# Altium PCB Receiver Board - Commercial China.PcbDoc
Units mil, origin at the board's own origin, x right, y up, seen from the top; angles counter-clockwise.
Board outline 2000 x 1000 mil, 2 copper layers (Top Layer, Bottom Layer); 23 components, 21 nets, 121 pads, 26 vias.
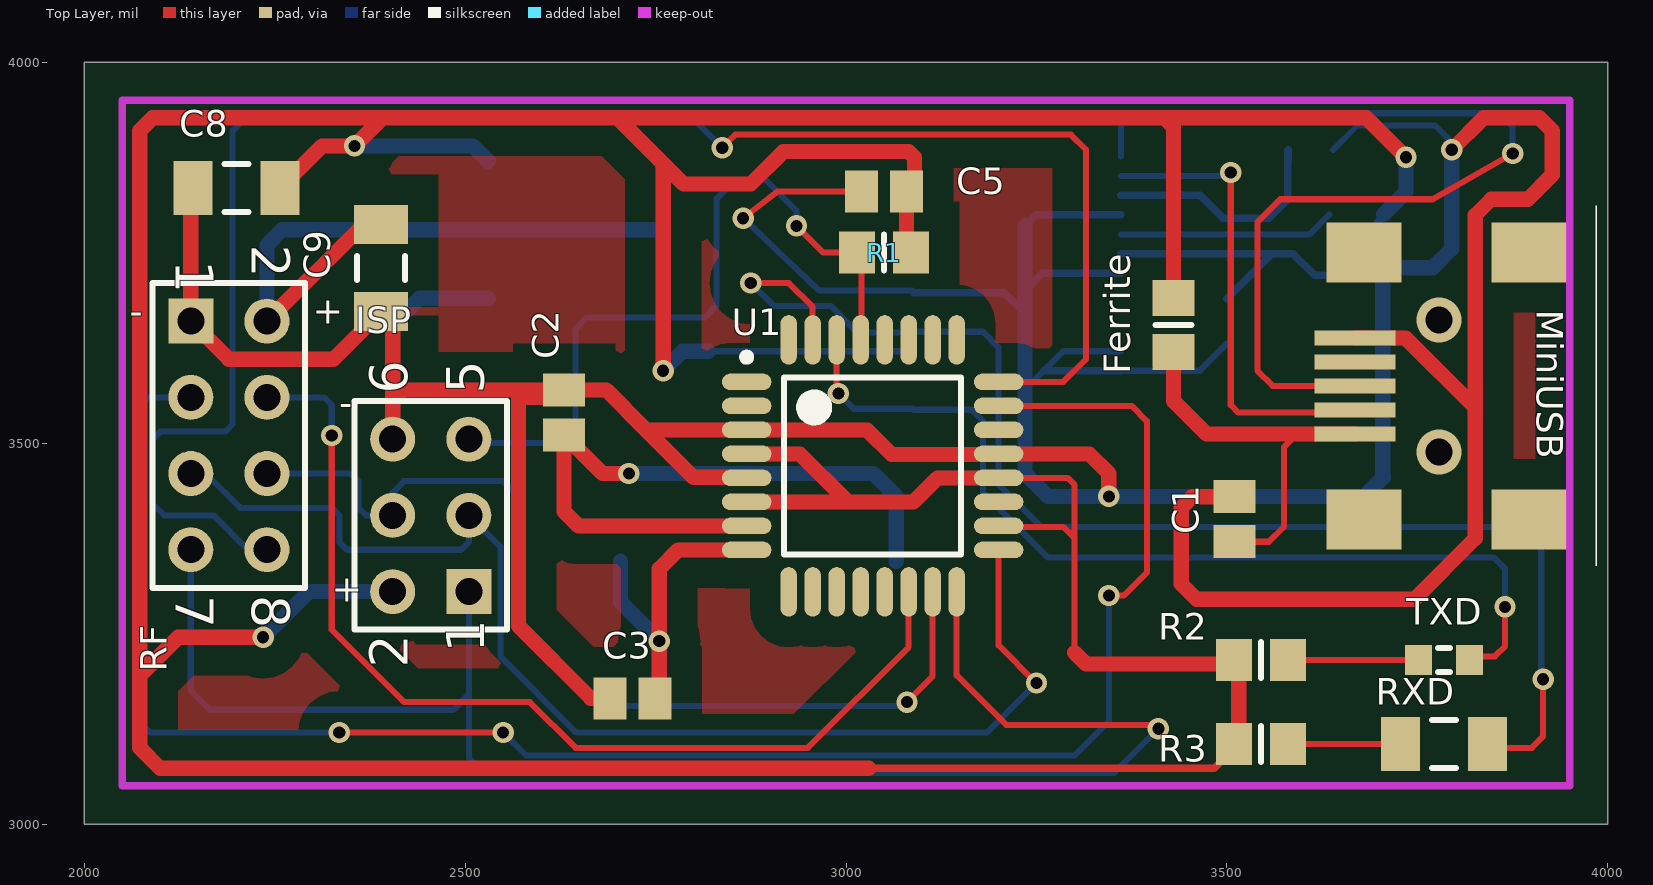
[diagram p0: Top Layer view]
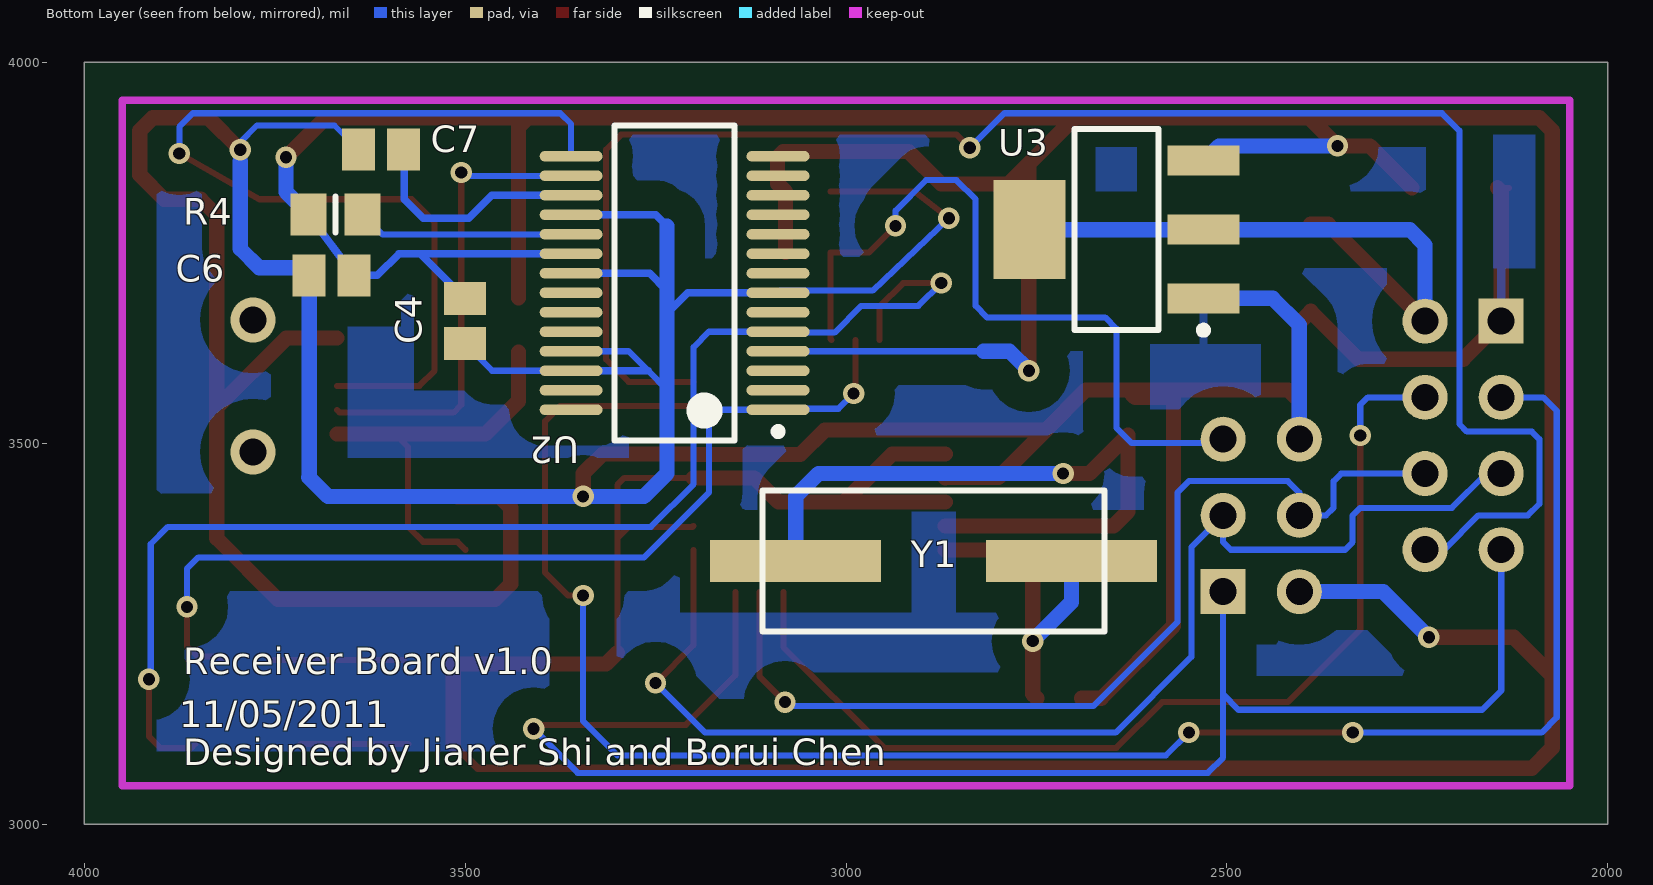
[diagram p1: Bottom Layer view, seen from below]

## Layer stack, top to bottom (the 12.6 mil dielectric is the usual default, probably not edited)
Top Layer: signal copper 1.4
Dielectric: dielectric 12.6, FR-4, Dk 4.8
Bottom Layer: signal copper 1.4

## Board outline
2000,3000 4000,3000 4000,4000 2000,4000

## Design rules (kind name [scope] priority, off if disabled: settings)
Clearance "Polygon Clearance" [InPolygon] p1: gap=40
Clearance [All] p2: gap=8.1
HoleSize [All] p1: absolutevalues=TRUE maxlimit=100 minlimit=16 maxpercent=80.000 minpercent=20.000
MinimumAnnularRing [All] p1: minimumring=6
PolygonConnect [All] p1: connectstyle=Relief reliefconductorwidth=10 reliefentries=4 polygonreliefangle="90 Angle"
RoutingVias [All] p1: holewidth=16 width=28 viastyle="Through Hole" minholewidth=16 minwidth=27 maxholewidth=16 maxwidth=35
SilkscreenOverComponentPads [All] p1: minsilkscreentomaskgap=10
SolderMaskExpansion [All] p1: expansion=4
Width [All] p1: maxlimit=50 minlimit=8 preferedwidth=8
26 further rules are at their usual default settings.

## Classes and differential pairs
component class "2.4ghz Receiver Board": C1 C2 C3 C4 C5 C6 C7 Ferrite ISP MiniUSB R1 R2 R3 R4 RF RXD TXD U1 U2 Y1
component class "5V to 3.3V": C8 C9 U3

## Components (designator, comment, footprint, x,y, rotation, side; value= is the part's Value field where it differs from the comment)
C1 "Cap Semi" CAPC2012L 3510,3400 r90 top
C2 "Cap Semi" CAPC2012L 2630,3540 r270 top
C3 "Cap Semi" CAPC2012L 2720,3165 r0 top
C4 "Cap Semi" CAPC2012L 3500,3660 r90 bottom
C5 "Cap Semi" CAPC2012L 3050,3830 r0 top
C6 "Cap Semi" CAPC2012L 3675,3720 r180 bottom
C7 "Cap Semi" CAPC2012L 3610,3885 r0 bottom
C8 "Cap Pol3 TANT" capc3216n 2200,3835 r180 top
C9 "Cap Pol3 TANT" capc3216n 2390,3730 r270 top
Ferrite "Ferrite Bead 1A" RESC2012N 3430,3655 r90 top
ISP "Header 3X2" HDR2X3 2505,3305 r90 top
MiniUSB "Mini USB" "MINI USB" 3985,3575 r180 top
R1 "Res3" RESC2012N 3050,3750 r0 top
R2 "Res3" RESC2012N 3545,3215 r0 top
R3 "Res3" RESC2012N 3545,3105 r0 top
R4 "Res3" RESC2012N 3670,3800 r180 bottom
RF "Header 4X2" HDR2X4 2140,3660 r270 top (schematic designator "RF Board")
RXD "LED2" RESC3216N 3785,3105 r0 top
TXD "LED2" RESC1608N 3785,3215 r0 top
U1 "ATmega8L-8AI" 32A_N 3035,3470 r0 top
U2 "FT232RL-Reel" SSOP-28_N 3225,3710 r0 bottom
U3 "LM1117MPX-3.3" MP04A_N 2645,3780 r0 bottom
Y1 "XTAL 8Mhz" "HC-49U - SMD" 2885,3345 r180 bottom

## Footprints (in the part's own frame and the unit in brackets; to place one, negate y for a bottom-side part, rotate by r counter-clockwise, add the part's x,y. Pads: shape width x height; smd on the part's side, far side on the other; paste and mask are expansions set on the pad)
32A_N [mm] "Thin QFP, 32-Leads, Body 7x7mm, Pitch 0.8mm, IPC Medium Density"
  oval 1.65x0.55 smd: 1(-4.2,2.8) 2(-4.2,2) 3(-4.2,1.2) 4(-4.2,0.4) 5(-4.2,-0.4) 6(-4.2,-1.2) 7(-4.2,-2) 8(-4.2,-2.8) 17(4.2,-2.8) 18(4.2,-2) 19(4.2,-1.2) 20(4.2,-0.4) 21(4.2,0.4) 22(4.2,1.2) 23(4.2,2) 24(4.2,2.8)
  oval 0.55x1.65 smd: 9(-2.8,-4.2) 10(-2,-4.2) 11(-1.2,-4.2) 12(-0.4,-4.2) 13(0.4,-4.2) 14(1.2,-4.2) 15(2,-4.2) 16(2.8,-4.2) 25(2.8,4.2) 26(2,4.2) 27(1.2,4.2) 28(0.4,4.2) 29(-0.4,4.2) 30(-1.2,4.2) 31(-2,4.2) 32(-2.8,4.2)
  silkscreen extent -4.32,-2.95 2.95,3.75, body extent -3.5,-3.5 3.5,3.5, height 1.2
CAPC2012L [mm] "Chip Capacitor, Body 2.0x1.3mm, IPC High Density"
  rect 1.1x1.4 smd: 1(-0.75,0) 2(0.75,0)
  body extent -1.1,-0.72 1.1,0.72, height 1.1
capc3216n [mm] "Chip Capacitor, Body 3.2x1.6mm, IPC Medium Density"
  rect 1.3x1.8 smd: 1(-1.45,0) 2(1.45,0)
  silkscreen extent -0.4,-0.8 0.4,0.8, body extent -1.7,-0.9 1.7,0.9, height 1.35
"HC-49U - SMD" [mm] "Quartz Crystal, Thru-Hole; 2 Leads; Body 11.35 x 4.65 x 13.46 mm (LxWxH max)"
  rect 5.7x1.4 smd: 1(-4.6,0) 2(4.6,0)
  silkscreen extent -5.7,-2.35 5.7,2.35
HDR2X3 [mm] "Connector; Header; 3x2 Position"
  rect 1.5x1.5 hole 0.9: 1(0,0)
  round 1.5 hole 0.9: 2(0,2.54) 3(2.54,0) 4(2.54,2.54) 5(5.08,0) 6(5.08,2.54)
  silkscreen extent -1.27,-1.27 6.35,3.81
HDR2X4 [mm] "Connector; Header; 4x2 Position"
  rect 1.5x1.5 hole 0.9: 1(0,0)
  round 1.5 hole 0.9: 2(0,2.54) 3(2.54,0) 4(2.54,2.54) 5(5.08,0) 6(5.08,2.54) 7(7.62,0) 8(7.62,2.54)
  silkscreen extent -1.27,-1.27 8.89,3.81
"MINI USB" [mm] "Digikey http://search.digikey.com/us/en/products/1734035-2/A31727CT-ND/773789"
  rect 2.7x0.5 smd: 1(8.05,1.6) 2(8.05,0.8) 3(8.05,0) 4(8.05,-0.8) 5(8.05,-1.6)
  rect 2.5x2 smd: NC(2.25,4.45) NC(2.25,-4.45) NC(7.75,-4.45) NC(7.75,4.45)
  silkscreen extent 0,-6 0,6
MP04A_N [mm] "SOT223, 4-Leads, Body 6.5x3.5mm, Pitch 2.3mm, Lead Span 7mm, IPC Medium Density"
  rect 2.4x1 smd: 1(-2.9,2.3) 2(-2.9,0) 3(-2.9,-2.3)
  rect 2.4x3.3 smd: 4(2.9,0)
  silkscreen extent -3.02,-3.35 1.4,3.47, body extent -1.85,-3.35 1.85,3.35, height 1.8
RESC1608N [mm] "Chip Resistor, Body 1.6x0.8mm, IPC Medium Density"
  rect 0.9x1 smd: 1(-0.85,0) 2(0.85,0)
  silkscreen extent -0.2,-0.4 0.2,0.4, body extent -0.85,-0.48 0.85,0.48, height 0.6
RESC2012N [mm] "Chip Resistor, Body 2.0x1.3mm, IPC Medium Density"
  rect 1.2x1.4 smd: 1(-0.9,0) 2(0.9,0)
  silkscreen extent 0,-0.6 0,0.6, body extent -1.07,-0.7 1.07,0.7, height 0.65
RESC3216N [mm] "Chip Resistor, Body 3.2x1.6mm, IPC Medium Density"
  rect 1.3x1.8 smd: 1(-1.45,0) 2(1.45,0)
  silkscreen extent -0.4,-0.8 0.4,0.8, body extent -1.68,-0.87 1.68,0.87, height 0.71
SSOP-28_N [mm] "SOP, 28-Leads, Body 10.2x5.3mm, Pitch 0.65mm, IPC Medium Density"
  oval 2.1x0.35 smd: 1(-3.45,4.225) 2(-3.45,3.575) 3(-3.45,2.925) 4(-3.45,2.275) 5(-3.45,1.625) 6(-3.45,0.975) 7(-3.45,0.325) 8(-3.45,-0.325) 9(-3.45,-0.975) 10(-3.45,-1.625) 11(-3.45,-2.275) 12(-3.45,-2.925) 13(-3.45,-3.575) 14(-3.45,-4.225) 15(3.45,-4.225) 16(3.45,-3.575) 17(3.45,-2.925) 18(3.45,-2.275) 19(3.45,-1.625) 20(3.45,-0.975) 21(3.45,-0.325) 22(3.45,0.325) 23(3.45,0.975) 24(3.45,1.625) 25(3.45,2.275) 26(3.45,2.925) 27(3.45,3.575) 28(3.45,4.225)
  silkscreen extent -3.57,-5.25 2,5.25, body extent -2.8,-5.25 2.8,5.25, height 2

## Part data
C1 C2 C3 C4 C5 C6 C7: "Capacitor (Semiconductor SIM Model)"
C8 C9: library part "Cap Pol3", "Polarized Capacitor (Surface Mount)"
Ferrite: library part "Ferrite Bead"
ISP: "Header, 3-Pin, Dual row"
R1 R2 R3 R4: "Resistor"
RF: "Header, 4-Pin, Dual row"
RXD TXD: "Typical RED, GREEN, YELLOW, AMBER GaAs LED"
U1: "8-Bit AVR Microcontroller with 8K Bytes of In-System Programmable Flash Memory"
U2: "USB UART Asynchronous Serial Data Transfer Chip, SSOP-28, Tape and Reel"
U3: "800mA Low-Dropout Linear Regulator, 4-pin SOT-223"
Y1: library part XTAL, "Crystal Oscillator"

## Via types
v1: diameter 28, hole 16, Top Layer to Bottom Layer, 24 vias
v2: diameter 59.06, hole 35.43, Top Layer to Bottom Layer, 2 vias

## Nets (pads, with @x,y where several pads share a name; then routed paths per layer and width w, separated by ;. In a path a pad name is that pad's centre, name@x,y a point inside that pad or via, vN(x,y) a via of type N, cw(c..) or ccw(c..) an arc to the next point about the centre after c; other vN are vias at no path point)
3.3VCC: C9.1 RF.2 U3.2 U3.4 | length 830.1
  Top Layer w20: RF.2 2367.09,3787.09 C9.1
  Bottom Layer w20: RF.2 2240,3760 2260,3780 U3.2 U3.4
5VCC: C4.2 C5.2 C6.2 C8.1 Ferrite.2 ISP.2 R1.2 R2.1 R3.1 R4.1 U1.4 U1.6 U1.18 U1.20 U2.4 U2.20 U3.3 | length 7987.9
  Top Layer w8: U1.18 3201.61,3390 3285,3390 3300,3375 ; U1.20 3290.75,3454.25 3300,3445 3300,3375 ; 3300,3225 3300,3375 ; R2.1@3510.47,3210 R2.1@3515.47,3215
  Top Layer w10: 3030,3073.1 3483.57,3073.1 R3.1@3515.47,3105 ; 3345,3926.9 3350,3931.9
  Top Layer w20: v1(2235,3245) 2123.1,3245 2073.1,3195 ; C8.1 2312.09,3890 v1(2355,3890) 2391.9,3926.9 ; v1(2760,3595) 2760,3866.9 ; U1.6 3088.5,3422.76 3120,3454.25 U1.20 ; U1.4 2939.25,3485.75 3000,3425 ; 3030,3073.1 2100,3073.1 2073.1,3100 2073.1,3195 ; R1.2@3079.53,3750 C5.2 3090,3840.47 3090,3875 3082.3,3882.7 2917.7,3882.7 2875,3840 2786.9,3840 2760,3866.9 ; 3300,3225 3315,3210 R2.1@3510.47,3210 ; Ferrite.2 3430,3875 3430,3915 3418.1,3926.9 ; R3.1@3515.47,3105 R2.1@3515.47,3215 ; v1(3735,3875) 3683.1,3926.9 3418.1,3926.9 ; 2073.1,3195 2073.1,3910 2090,3926.9 2391.9,3926.9 ; 2391.9,3926.9 2700,3926.9 ; 2700,3926.9 3345,3926.9 3418.1,3926.9 ; 2700,3926.9 2760,3866.9
  Bottom Layer w8: 2819.57,3620.43 U2.4
  Bottom Layer w10: U2.20 3558.86,3748.39 ; C4.2 3558.86,3748.39 ; C6.2@3645.47,3740.04 C6.2 ; R4.1 C6.2 ; 3558.86,3748.39 3586.61,3748.39 3615,3720 C6.2
  Bottom Layer w20: v1(2235,3245) 2295,3305 ISP.2 ; v1(2355,3890) 2510.28,3890 2530.28,3870 U3.3 ; v1(2760,3595) 2785.43,3620.43 2819.57,3620.43 ; R4.1 3735,3829.57 v1(3735,3875)
\R\E\S\E\T\: ISP.5 R1.1 U1.29 | length 984.8
  Top Layer w8: v1(2935,3785) 2970,3750 3020.47,3750 3020.47,3636.57 U1.29
  Bottom Layer w8: ISP.5 2510,3500 2625,3500 2645,3520 2645,3650 2660,3665 2815,3665 2830,3680 2830,3820 2855,3845 2895,3845 2935,3805 v1(2935,3785)
CE: RF.3 U1.23 | length 2428.8
  Top Layer w8: v1(2335,3120) v1(2550,3120) ; U1.23 3375,3548.74 3395,3528.74 3395,3330 3365,3300 v1(3345,3300)
  Bottom Layer w8: RF.3 2085,3560 2067.1,3542.1 2067.1,3140 2087.1,3120 v1(2335,3120) ; v1(2550,3120) 2580,3090 3300,3090 3345,3135 v1(3345,3300)
CSN: RF.4 U1.14 | length 1332.8
  Top Layer w8: v1(2325,3510) 2325,3255 2420,3160 2585,3160 2645,3100 2950,3100 3082.24,3232.24 U1.14
  Bottom Layer w8: RF.4 2315,3560 2325,3550 v1(2325,3510)
GND: C1.2 C2.1 C3.1 C4.1 C5.1 C6.1 C7.2 C8.2 C9.2 ISP.6 MiniUSB.5 RF.1 U1.3 U1.5 U1.21 U2.7 U2.18 U2.21 U2.25 U2.26 U3.1 | length 6968.4
  Top Layer w8: C8.2@2130,3835 C8.2@2144.88,3835 ; v1(2865,3795) 2910,3830 C5.1
  Top Layer w20: C8.2@2144.88,3835 2140,3830.12 RF.1 2190,3610 2327.09,3610 C9.2 2405,3657.91 2405,3555 ; ISP.6 2405,3555 ; C3.1 2665,3165 2570,3260 2570,3560 2620.47,3560 C2.1 ; U1.5 2868.9,3455 2800,3455 2737.76,3517.24 ; v1(3345,3430) 3345,3460 3319.25,3485.75 U1.21 3199.61,3485 3060,3485 3027.76,3517.24 U1.3 2737.76,3517.24 ; C1.2 3454.53,3429.53 3440,3415 3440,3315 3460,3295 3745.93,3295 3825.93,3375 3825.93,3546.63 ; MiniUSB.5 3734.57,3637.99 3825.93,3546.63 ; v1(3795,3885) 3836.9,3926.9 3910,3926.9 3926.9,3910 3926.9,3851.9 3895,3820 3846.9,3820 3825.93,3799.03 3825.93,3546.63 ; 2405,3555 2419.53,3569.53 C2.1 ; C2.1 2685.47,3569.53 2737.76,3517.24
  Bottom Layer w8: v1(2865,3795) 2965,3700 U2.7@3086.38,3700 ; 3235,3570 3259.84,3594.84 3285.43,3620.43 U2.25 U2.25@3360.39,3620 ; U2.26 3464.37,3594.84 C4.1 ; C7.2 3671.33,3916.8 3773.2,3916.8 3795,3895 v1(3795,3885)
  Bottom Layer w10: U2.7 3207.8,3697.2 3235,3670 ; 3235,3700 3257.8,3722.8 U2.21 ; 3235,3785 3249.57,3799.57 U2.18 ; 3259.84,3594.84 U2.26
  Bottom Layer w20: ISP.6@2400,3510 ISP.6 2405,3655 2440,3690 2530.28,3690 U3.1 ; 3235,3785 3235,3700 3235,3670 3235,3570 3235,3460 3265,3430 v1(3345,3430) 3680,3430 3705,3455 3704.53,3455.47 C6.1 3714.53,3730 3770,3730 3795,3755 3795,3870
IRQ: RF.8 U1.24 | length 2323.8
  Top Layer w8: v1(2837.5,3887.5) 2854.8,3904.8 3295.2,3904.8 3315,3885 3315,3610 3285.24,3580.24 U1.24
  Bottom Layer w8: RF.8 2215,3360 2170,3405 2105,3405 2090,3420 2090,3505 2100,3515 2185,3515 2195,3525 2195,3910 2217.9,3932.9 2792.1,3932.9 v1(2837.5,3887.5)
MISO: ISP.1 RF.7 U1.16 | length 2127.2
  Top Layer w8: U1.16 3145.24,3195 3210.24,3130 3405,3130 v1(3410,3125)
  Bottom Layer w8: RF.7 2140,3175 2165,3150 2485,3150 2505,3170 ; ISP.1 2505,3170 ; v1(3410,3125) 3352.1,3067.1 2525,3067.1 2505,3087.1 2505,3170
MOSI: ISP.4 RF.6 U1.15 | length 1302
  Top Layer w8: v1(3080,3160) 3113.74,3193.74 U1.15
  Bottom Layer w8: RF.6 2350,3460 2360,3450 2360,3415 2370,3405 ISP.4 2405,3435 2420,3450 2550,3450 2565,3435 2565,3265 2675,3155 3075,3155 v1(3080,3160)
NetC1_1: C1.1 Ferrite.1 MiniUSB.1 | length 537.1
  Top Layer w8: C1.1@3499.53,3360 C1.1 3555,3370.47 3575,3390.47 3575,3495 3592.01,3512.01
  Top Layer w20: Ferrite.1 3430,3555 3472.99,3512.01 3592.01,3512.01 MiniUSB.1
NetC2_2: C2.2 U1.7 Y1.1 | length 902.3
  Top Layer w20: v1(2715,3460) 2680.47,3460 2655.47,3485 C2.2 2630,3435 2630,3410 2648.74,3391.26 U1.7
  Bottom Layer w20: v1(2715,3460) 3036.1,3460 3066.1,3430 Y1.1
NetC3_2: C3.2 U1.8 Y1.2 | length 423.3
  Top Layer w20: C3.2 2755,3170.47 v1(2755,3240) 2755,3335 2779.76,3359.76 U1.8
  Bottom Layer w20: Y1.2 2703.9,3291.1 v1(2755,3240)
NetC7_1: C7.1 U2.17 | length 320.7
  Bottom Layer w10: U2.17 3464.84,3825.16 3495,3795 3555,3795 3580,3820 3580,3884.53 C7.1 C7.1@3580.47,3871.5
NetR2_2: R2.2 TXD.1 | length 171.1
  Top Layer w8: R2.2 TXD.1
NetR3_2: R3.2 RXD.1 | length 141.6
  Top Layer w8: R3.2@3574.53,3105 RXD.1@3716.1,3105
NetR4_2: R4.2 U2.19 | length 284.5
  Bottom Layer w8: U2.19 3608.54,3773.98 R4.2
NetRXD_2: RXD.2 U1.31 U2.5 | length 1746.1
  Top Layer w8: v1(2875,3710) 2925,3710 2956.26,3678.74 U1.31 ; RXD.2@3853.9,3105 3858.9,3100 3900,3100 3915,3115 v1(3915,3190)
  Bottom Layer w8: v1(2875,3710) 2905,3680 2980,3680 3015,3645 3088.15,3645 U2.5 3180,3646.02 3200,3626.02 3200,3446.1 3256.1,3390 3890,3390 3912.5,3367.5 3912.5,3192.5 v1(3915,3190)
NetTXD_2: TXD.2 U1.30 U2.1 | length 1252.3
  Top Layer w8: U1.30 2987.76,3567.24 v1(2990,3565) ; TXD.2 3823.46,3220 3851.73,3220 3865,3233.27 v1(3865,3285)
  Bottom Layer w8: v1(2990,3565) 3010,3545 3087.83,3545 U2.1 3165,3543.66 3180,3528.66 3180,3435 3265,3350 3850,3350 3865,3335 v1(3865,3285)
SCK: ISP.3 RF.5 U1.17 | length 1635.7
  Top Layer w8: U1.17 3200.35,3234.65 v1(3250,3185)
  Bottom Layer w8: RF.5 2160,3460 2205,3415 2325,3415 2335,3405 2335,3370 2345,3360 2495,3360 2505,3370 ISP.3 2546.63,3363.37 2546.63,3219.47 2646.1,3120 3185,3120 v1(3250,3185)
USBDM: MiniUSB.2 U2.16 | length 619.6
  Top Layer w8: v1(3505,3855) 3505,3550 3515,3540 3664.57,3540 MiniUSB.2
  Bottom Layer w8: U2.16 3500.75,3850.75 v1(3505,3855)
USBDP: MiniUSB.3 U2.15 | length 1299.6
  Top Layer w8: MiniUSB.3 3560,3575 3540,3595 3540,3790 3570,3820 3770,3820 v1(3875,3880)
  Bottom Layer w8: U2.15 3360.83,3918.73 3375,3932.9 3857.1,3932.9 3875,3915 v1(3875,3880)
pads on no net: MiniUSB.4 MiniUSB.NC U1.1 U1.2 U1.9 U1.10 U1.11 U1.12 U1.13 U1.19 U1.22 U1.25 U1.26 U1.27 U1.28 U1.32 U2.2 U2.3 U2.6 U2.8 U2.9 U2.10 U2.11 U2.12 U2.13 U2.14 U2.22 U2.23 U2.24 U2.27 U2.28
copper on no net:
  other v2: 3778.31,3488.39 3778.31,3661.61

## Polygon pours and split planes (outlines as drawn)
GND on Bottom Layer "bottom" (solid, pour order 4): 2025,3975 3975,3975 3975,3025 2025,3025
GND on Top Layer "Top Layer-No Net" (solid, pour order 2): 2025,3975 3975,3975 3975,3025 2025,3025

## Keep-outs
Keep-Out Layer:
  lines w10: 2050,3050 3950,3050 3950,3950 2050,3950 2050,3050

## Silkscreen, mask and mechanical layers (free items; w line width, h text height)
Top Overlay:
  text "-" at 2060,3645 h60
  text "+" at 2300,3645 h60
  text "-" at 2335,3525 h60
  text "+" at 2325,3280 h60
Bottom Overlay:
  text "Receiver Board v1.0" at 3870,3185 h60
  text "11/05/2011" at 3875,3115 h60
  text "Designed by Jianer Shi and Borui Chen" at 3870,3065 h60

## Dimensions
2050,3050 to 3950,3050 on Mechanical 1
2050,3050 to 2050,3950 on Mechanical 1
